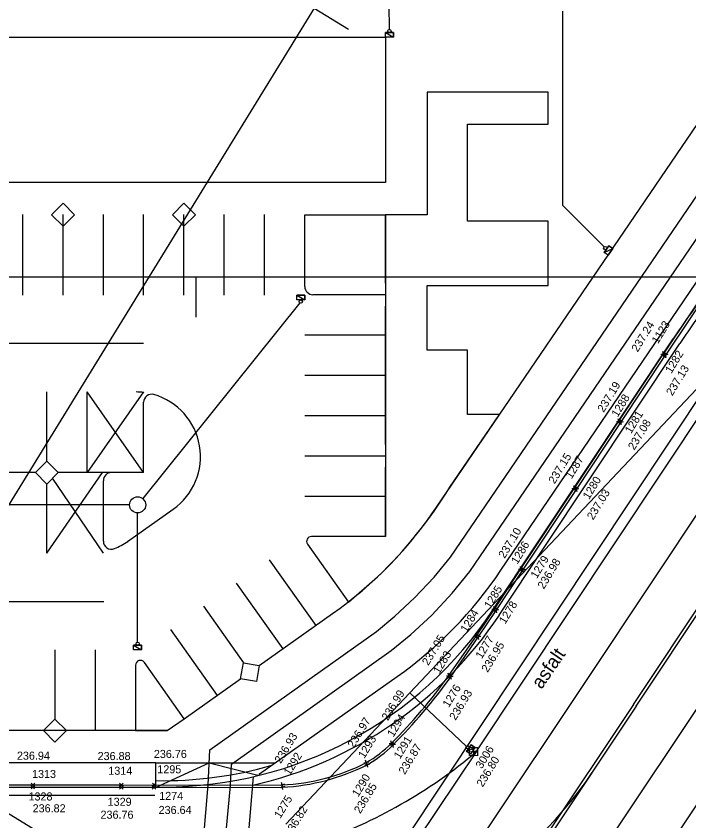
# Model space of a CAD drawing. Extents: x -264205 to -263615, y -1242401 to -1242031.
# Drawn here: x -263824.98 to -263783.24, y -1242303.58 to -1242253.67 of the extents above; entities that cross this region are included whole.
import ezdxf

# ---------------------------------------------------------------- set-up
doc = ezdxf.new("R2010")
doc.units = 0
for name, color, linetype in [('BODY_SYMBOL A CISLO_2-1', 7, 'Continuous'), ('BODY_SYMBOL A CISLO_2-2', 7, 'Continuous'), ('BODY_VYSKA_2-1', 7, 'Continuous'), ('BODY_VYSKA_2-2', 7, 'Continuous'), ('KOORDINACNA_SITUACIA_DSP', 7, 'Continuous'), ('POPIS', 7, 'Continuous'), ('PROJEKT_DRS_TDZ_VODOROVNE', 7, 'Continuous'), ('RAM_NA_TLAC_1-250_SITUACIA_2-1', 7, 'Continuous'), ('RAM_NA_TLAC_1-250_SITUACIA_2-2', 7, 'Continuous'), ('SO_20-1_OBRUBNIKY_DOLNA_HRANA', 7, 'Continuous'), ('SO_20-1_OBRUBNIKY_HORNA_HRANA', 7, 'Continuous'), ('SO_20-1_UV', 7, 'Continuous')]:
    doc.layers.add(name, color=color, linetype=linetype)

msp = doc.modelspace()

# ---------------------------------------------------------------- linework, layer by layer
at = {"layer": 'BODY_SYMBOL A CISLO_2-1'}
for p, q in [((-263824.056, -1242301.597), (-263823.834, -1242301.377)), ((-263823.834, -1242301.597), (-263824.056, -1242301.377)), ((-263824.051, -1242301.454), (-263823.829, -1242301.232)), ((-263823.829, -1242301.454), (-263824.051, -1242301.232)), ((-263818.567, -1242301.463), (-263818.345, -1242301.242)), ((-263818.345, -1242301.463), (-263818.567, -1242301.242)), ((-263818.562, -1242301.606), (-263818.341, -1242301.384)), ((-263818.341, -1242301.606), (-263818.562, -1242301.384)), ((-263816.53, -1242301.615), (-263816.309, -1242301.394)), ((-263816.309, -1242301.615), (-263816.53, -1242301.394)), ((-263816.524, -1242301.468), (-263816.302, -1242301.248)), ((-263816.302, -1242301.468), (-263816.524, -1242301.248))]:
    msp.add_line(p, q, dxfattribs=at)
at = {"layer": 'BODY_SYMBOL A CISLO_2-2'}
for p, q in [((-263784.785, -1242274.779), (-263784.859, -1242274.475)), ((-263784.783, -1242274.775), (-263784.857, -1242274.471)), ((-263784.67, -1242274.59), (-263784.974, -1242274.664)), ((-263784.668, -1242274.586), (-263784.972, -1242274.66)), ((-263784.548, -1242274.667), (-263784.852, -1242274.741)), ((-263784.543, -1242274.66), (-263784.847, -1242274.734)), ((-263784.663, -1242274.856), (-263784.737, -1242274.552)), ((-263784.658, -1242274.849), (-263784.732, -1242274.545)), ((-263787.432, -1242278.753), (-263787.736, -1242278.827)), ((-263787.547, -1242278.942), (-263787.621, -1242278.638)), ((-263787.31, -1242278.835), (-263787.614, -1242278.909)), ((-263787.425, -1242279.024), (-263787.499, -1242278.72)), ((-263790.188, -1242282.911), (-263790.492, -1242282.985)), ((-263790.303, -1242283.1), (-263790.377, -1242282.796)), ((-263790.064, -1242282.985), (-263790.368, -1242283.059)), ((-263790.179, -1242283.174), (-263790.253, -1242282.87)), ((-263793.507, -1242287.918), (-263793.811, -1242287.992)), ((-263793.622, -1242288.107), (-263793.696, -1242287.803)), ((-263793.501, -1242288.186), (-263793.575, -1242287.882)), ((-263793.386, -1242287.997), (-263793.69, -1242288.071)), ((-263795.158, -1242290.407), (-263795.462, -1242290.481)), ((-263795.273, -1242290.596), (-263795.347, -1242290.292)), ((-263795.037, -1242290.487), (-263795.341, -1242290.561)), ((-263795.152, -1242290.676), (-263795.226, -1242290.372)), ((-263796.386, -1242292.251), (-263796.46, -1242291.947)), ((-263796.271, -1242292.062), (-263796.575, -1242292.136)), ((-263796.151, -1242292.143), (-263796.455, -1242292.217)), ((-263796.266, -1242292.332), (-263796.34, -1242292.028)), ((-263798.095, -1242294.725), (-263798.169, -1242294.421)), ((-263797.98, -1242294.536), (-263798.284, -1242294.61)), ((-263797.861, -1242294.617), (-263798.165, -1242294.691)), ((-263797.976, -1242294.806), (-263798.05, -1242294.502)), ((-263801.54, -1242298.73), (-263801.844, -1242298.804)), ((-263801.441, -1242298.833), (-263801.745, -1242298.907)), ((-263801.655, -1242298.919), (-263801.729, -1242298.615)), ((-263801.556, -1242299.022), (-263801.63, -1242298.718)), ((-263796.449, -1242299.249), (-263796.753, -1242299.323)), ((-263796.564, -1242299.438), (-263796.638, -1242299.134)), ((-263803.105, -1242299.929), (-263803.409, -1242300.003)), ((-263803.22, -1242300.118), (-263803.294, -1242299.814)), ((-263803.152, -1242300.246), (-263803.226, -1242299.942)), ((-263803.037, -1242300.057), (-263803.341, -1242300.131)), ((-263808.324, -1242301.307), (-263808.628, -1242301.381)), ((-263808.313, -1242301.451), (-263808.617, -1242301.525)), ((-263808.439, -1242301.496), (-263808.513, -1242301.192)), ((-263808.428, -1242301.64), (-263808.502, -1242301.336))]:
    msp.add_line(p, q, dxfattribs=at)
at = {"layer": 'KOORDINACNA_SITUACIA_DSP'}
for p, q in [((-263822.88, -1242337.914), (-263734.49, -1242204.937)), ((-263794.898, -1242288.032), (-263742.736, -1242211.145)), ((-263798.899, -1242284.125), (-263751.864, -1242215.081)), ((-263801.822, -1242254.497), (-263801.837, -1242252.972)), ((-263791.063, -1242265.427), (-263791.063, -1242253.362)), ((-263802.071, -1242254.697), (-263801.571, -1242254.697)), ((-263802.071, -1242254.987), (-263802.071, -1242254.697)), ((-263802.071, -1242254.697), (-263801.571, -1242254.987)), ((-263802.071, -1242254.697), (-263801.571, -1242254.987)), ((-263801.571, -1242254.697), (-263802.071, -1242254.697)), ((-263801.571, -1242254.987), (-263802.071, -1242254.987)), ((-263801.571, -1242254.697), (-263801.571, -1242254.987)), ((-263801.571, -1242254.987), (-263801.571, -1242254.697)), ((-263788.502, -1242267.989), (-263791.063, -1242265.427)), ((-263807.068, -1242270.447), (-263807.068, -1242265.987)), ((-263807.068, -1242265.987), (-263802.068, -1242265.987)), ((-263802.068, -1242270.24), (-263802.068, -1242265.987)), ((-263788.491, -1242268.322), (-263788.207, -1242267.91)), ((-263788.207, -1242267.91), (-263788.491, -1242268.322)), ((-263788.207, -1242267.91), (-263787.968, -1242268.075)), ((-263787.968, -1242268.075), (-263788.207, -1242267.91)), ((-263788.491, -1242268.322), (-263787.968, -1242268.075)), ((-263788.491, -1242268.322), (-263787.968, -1242268.075)), ((-263788.252, -1242268.487), (-263788.491, -1242268.322)), ((-263787.968, -1242268.075), (-263788.252, -1242268.487)), ((-263807.568, -1242270.982), (-263807.068, -1242270.982)), ((-263807.568, -1242271.272), (-263807.568, -1242270.982)), ((-263807.568, -1242270.982), (-263807.068, -1242271.272)), ((-263807.568, -1242270.982), (-263807.068, -1242271.272)), ((-263807.068, -1242270.982), (-263807.568, -1242270.982)), ((-263807.068, -1242270.982), (-263807.068, -1242271.272)), ((-263807.068, -1242271.272), (-263807.068, -1242270.982)), ((-263802.068, -1242270.947), (-263806.568, -1242270.947)), ((-263807.38, -1242271.45), (-263817.128, -1242283.593)), ((-263807.068, -1242271.272), (-263807.568, -1242271.272)), ((-263802.068, -1242280.24), (-263802.068, -1242271.654)), ((-263795.416, -1242290.541), (-263784.214, -1242273.68)), ((-263780.353, -1242274.236), (-263808.248, -1242303.783)), ((-263817.068, -1242281.982), (-263817.068, -1242277.62)), ((-263817.068, -1242281.982), (-263819.068, -1242281.982)), ((-263802.068, -1242285.947), (-263802.068, -1242281.654)), ((-263819.568, -1242286.231), (-263819.568, -1242282.482)), ((-263817.941, -1242283.982), (-263870.324, -1242283.982)), ((-263817.941, -1242283.982), (-263870.324, -1242283.982)), ((-263818.06, -1242286.248), (-263815.232, -1242284.248)), ((-263817.441, -1242292.492), (-263817.441, -1242284.482)), ((-263809.895, -1242293.947), (-263805.344, -1242290.728)), ((-263817.691, -1242292.692), (-263817.191, -1242292.692)), ((-263817.691, -1242292.982), (-263817.691, -1242292.692)), ((-263817.691, -1242292.692), (-263817.191, -1242292.982)), ((-263817.691, -1242292.692), (-263817.191, -1242292.982)), ((-263817.191, -1242292.692), (-263817.691, -1242292.692)), ((-263817.191, -1242292.982), (-263817.691, -1242292.982)), ((-263817.191, -1242292.692), (-263817.191, -1242292.982)), ((-263817.191, -1242292.982), (-263817.191, -1242292.692)), ((-263814.555, -1242297.242), (-263811.05, -1242294.763)), ((-263809.875, -1242300.669), (-263801.342, -1242294.634)), ((-263797.048, -1242298.952), (-263800.558, -1242295.638)), ((-263815.601, -1242297.982), (-263917.08, -1242297.982)), ((-263797.029, -1242299.286), (-263796.75, -1242298.871)), ((-263796.75, -1242298.871), (-263797.029, -1242299.286)), ((-263796.75, -1242298.871), (-263796.51, -1242299.032)), ((-263796.51, -1242299.032), (-263796.75, -1242298.871)), ((-263797.029, -1242299.286), (-263796.51, -1242299.032)), ((-263797.029, -1242299.286), (-263796.51, -1242299.032)), ((-263796.788, -1242299.448), (-263797.029, -1242299.286)), ((-263796.51, -1242299.032), (-263796.788, -1242299.448)), ((-263816.308, -1242299.982), (-263918.049, -1242299.982)), ((-263816.308, -1242301.482), (-263816.308, -1242299.982)), ((-263816.308, -1242299.982), (-263808.904, -1242299.982)), ((-263809.906, -1242300.757), (-263809.875, -1242300.669)), ((-263914.08, -1242301.482), (-263815.822, -1242301.482))]:
    msp.add_line(p, q, dxfattribs=at)
for points in [[(-263802.068, -1242263.988), (-263834.256, -1242263.984), (-263849.468, -1242254.985), (-263802.068, -1242254.987)], [(-263822.068, -1242265.279), (-263821.361, -1242265.986), (-263822.068, -1242266.694), (-263822.775, -1242265.986)], [(-263814.568, -1242265.279), (-263813.861, -1242265.986), (-263814.568, -1242266.693), (-263815.275, -1242265.986)], [(-263823.068, -1242281.275), (-263822.361, -1242281.982), (-263823.068, -1242282.689), (-263823.775, -1242281.982)], [(-263810.881, -1242293.778), (-263809.895, -1242293.947), (-263810.064, -1242294.932), (-263811.05, -1242294.763)], [(-263822.568, -1242297.275), (-263821.861, -1242297.982), (-263822.568, -1242298.689), (-263823.275, -1242297.982)]]:
    msp.add_lwpolyline(points, close=True, dxfattribs=at)
for points in [[(-263798.064, -1242282.882), (-263794.987, -1242278.383), (-263796.968, -1242278.382), (-263796.968, -1242274.382), (-263799.468, -1242274.382), (-263799.468, -1242270.382), (-263791.968, -1242270.382), (-263791.968, -1242266.382), (-263796.968, -1242266.382), (-263796.968, -1242260.382), (-263791.968, -1242260.382), (-263791.968, -1242258.382), (-263799.468, -1242258.382), (-263799.468, -1242265.987), (-263802.068, -1242265.987)], [(-263802.068, -1242265.987), (-263802.068, -1242270.24), (-263802.068, -1242270.947), (-263802.068, -1242271.654), (-263802.068, -1242273.447), (-263802.068, -1242275.947), (-263802.068, -1242278.447), (-263802.068, -1242280.24), (-263802.068, -1242280.24), (-263802.068, -1242281.654), (-263802.068, -1242283.447), (-263802.068, -1242285.947), (-263806.656, -1242285.943)], [(-263806.901, -1242286.416), (-263804.349, -1242290.024), (-263802.552, -1242288.44)], [(-263817.568, -1242293.926), (-263817.568, -1242297.982), (-263815.601, -1242297.982), (-263814.555, -1242297.242), (-263817.023, -1242293.753)], [(-263816.327, -1242301.51), (-263813.002, -1242299.982), (-263809.906, -1242300.757)]]:
    msp.add_lwpolyline(points, dxfattribs=at)
for centre, radius in [((-263801.821, -1242254.597), 0.1), ((-263788.431, -1242268.059), 0.1), ((-263807.318, -1242271.372), 0.1), ((-263817.441, -1242283.982), 0.5), ((-263817.441, -1242292.592), 0.1), ((-263796.975, -1242299.02), 0.1)]:
    msp.add_circle(centre, radius, dxfattribs=at)
for centre, radius, start, end in [((-263806.568, -1242270.447), 0.5, 180, 270), ((-263742.568, -1242301.35), 50, 142.3688, 146.3992), ((-263816.568, -1242277.62), 0.5, 73.8446, 180), ((-263817.542, -1242280.982), 4, 305.2702, 73.8446), ((-263819.068, -1242282.482), 0.5, 90, 180), ((-263821.806, -1242268.304), 27.86, 313.7192, 328.4502), ((-263820.069, -1242269.909), 25.5, 305.2702, 326.1165), ((-263806.656, -1242286.243), 0.3, 89.9436, 215.2702), ((-263819.068, -1242286.231), 0.5, 180, 291.8332), ((-263820.369, -1242282.982), 4, 291.8332, 305.2702), ((-263816.067, -1242273.815), 25.5, 305.2702, 326.1165), ((-263815.822, -1242276.982), 24.5, 270, 326.3992), ((-263817.268, -1242293.926), 0.3, 35.2702, 180), ((-263815.836, -1242276.967), 24.119, 268.8787, 286.1798)]:
    msp.add_arc(centre, radius, start, end, dxfattribs=at)
at = {"layer": 'PROJEKT_DRS_TDZ_VODOROVNE'}
for p, q in [((-263824.568, -1242270.982), (-263824.568, -1242265.982)), ((-263822.068, -1242270.982), (-263822.068, -1242265.982)), ((-263819.568, -1242270.982), (-263819.568, -1242265.982)), ((-263817.068, -1242270.982), (-263817.068, -1242265.982)), ((-263814.568, -1242270.982), (-263814.568, -1242265.982)), ((-263812.068, -1242270.982), (-263812.068, -1242265.982)), ((-263809.568, -1242270.982), (-263809.568, -1242265.982)), ((-263807.068, -1242273.447), (-263802.068, -1242273.447)), ((-263796.435, -1242299.302), (-263779.243, -1242273.429)), ((-263817.068, -1242273.982), (-263917.477, -1242273.982)), ((-263795, -1242290.817), (-263783.807, -1242273.971)), ((-263789.385, -1242294.564), (-263776.537, -1242275.228)), ((-263807.068, -1242275.947), (-263802.068, -1242275.947)), ((-263823.068, -1242281.275), (-263823.068, -1242276.982)), ((-263820.568, -1242281.982), (-263820.568, -1242276.982)), ((-263817.068, -1242276.982), (-263820.568, -1242281.982)), ((-263817.068, -1242281.982), (-263820.568, -1242276.982)), ((-263786.678, -1242296.363), (-263773.83, -1242277.027)), ((-263786.512, -1242296.474), (-263773.663, -1242277.138)), ((-263807.068, -1242278.447), (-263802.068, -1242278.447)), ((-263818.504, -1242350.278), (-263771.023, -1242279.037)), ((-263807.068, -1242280.947), (-263802.068, -1242280.947)), ((-263823.775, -1242281.982), (-263829.861, -1242281.982)), ((-263823.068, -1242286.982), (-263819.614, -1242281.982)), ((-263818.068, -1242281.982), (-263822.361, -1242281.982)), ((-263819.568, -1242286.982), (-263822.714, -1242282.336)), ((-263823.068, -1242286.982), (-263823.068, -1242282.689)), ((-263807.068, -1242283.447), (-263802.068, -1242283.447)), ((-263809.278, -1242287.386), (-263806.39, -1242291.468)), ((-263811.319, -1242288.829), (-263808.432, -1242292.912)), ((-263819.531, -1242289.994), (-263917.477, -1242289.994)), ((-263813.36, -1242290.273), (-263810.881, -1242293.778)), ((-263813.36, -1242290.273), (-263810.881, -1242293.778)), ((-263815.401, -1242291.717), (-263812.514, -1242295.799)), ((-263822.568, -1242292.982), (-263822.568, -1242297.275)), ((-263820.068, -1242292.982), (-263820.068, -1242297.982)), ((-263824.083, -1242346.553), (-263789.385, -1242294.564)), ((-263786.678, -1242296.363), (-263806.091, -1242325.442)), ((-263786.512, -1242296.474), (-263805.925, -1242325.553)), ((-263796.435, -1242299.302), (-263802.558, -1242308.383)), ((-263781.086, -1242300.054), (-263792.626, -1242317.328)), ((-263810.915, -1242308.545), (-263810.255, -1242300.841)), ((-263913.857, -1242301.982), (-263816.374, -1242301.982))]:
    msp.add_line(p, q, dxfattribs=at)
for points in [[(-263831.211, -1242326.873), (-263816.19, -1242319.41), (-263814.291, -1242315.804), (-263813.06, -1242301.353), (-263812.968, -1242299.181), (-263802.618, -1242291.831), (-263801.478, -1242290.893), (-263800.257, -1242289.755), (-263799.049, -1242288.464), (-263798.027, -1242287.218), (-263749.798, -1242216.488), (-263742.736, -1242211.145)], [(-263830.6, -1242328.105), (-263815.26, -1242320.378), (-263813.062, -1242316.188), (-263811.682, -1242301.389), (-263811.608, -1242300.055), (-263801.705, -1242293.023), (-263800.489, -1242292.021), (-263799.197, -1242290.817), (-263797.92, -1242289.454), (-263796.825, -1242288.118), (-263748.697, -1242217.536), (-263741.831, -1242212.341)]]:
    msp.add_lwpolyline(points, dxfattribs=at)
for centre, radius, start, end in [((-263742.161, -1242301.641), 50, 142.3688, 146.3992), ((-263817.542, -1242280.982), 4, 83.1966, 90), ((-263815.822, -1242276.982), 25, 282.7622, 326.3992), ((-263816.477, -1242275.476), 31.135, 289.1139, 310.0684), ((-263809.228, -1242287.295), 24, 270.4085, 326.3969)]:
    msp.add_arc(centre, radius, start, end, dxfattribs=at)
at = {"layer": 'RAM_NA_TLAC_1-250_SITUACIA_2-1'}
msp.add_line((-263813.833, -1242269.835), (-263813.833, -1242272.335), dxfattribs=at)
msp.add_lwpolyline([(-264151.333, -1242269.835), (-263718.833, -1242269.835), (-263718.833, -1242344.085), (-264151.333, -1242344.085)], close=True, dxfattribs=at)
at = {"layer": 'RAM_NA_TLAC_1-250_SITUACIA_2-2'}
msp.add_line((-263806.493, -1242253.175), (-263804.363, -1242254.485), dxfattribs=at)
msp.add_lwpolyline([(-263834.004, -1242297.889), (-263756.71, -1242172.264), (-263693.471, -1242211.173), (-263770.766, -1242336.799)], close=True, dxfattribs=at)
at = {"layer": 'SO_20-1_OBRUBNIKY_DOLNA_HRANA'}
for points in [[(-263753.129, -1242233.288), (-263758.555, -1242239.941), (-263762.992, -1242245.362), (-263766.809, -1242249.987), (-263769.992, -1242253.855), (-263773.801, -1242258.482), (-263776.883, -1242263.085), (-263780.236, -1242268.055), (-263784.695, -1242274.697)], [(-263798.013, -1242294.654), (-263796.303, -1242292.18), (-263795.189, -1242290.524), (-263793.538, -1242288.034), (-263790.216, -1242283.022), (-263787.462, -1242278.872), (-263784.7, -1242274.704)], [(-263913.884, -1242301.489), (-263907.893, -1242301.489), (-263900.89, -1242301.488), (-263893.898, -1242301.483), (-263886.917, -1242301.473), (-263879.922, -1242301.465), (-263872.91, -1242301.469), (-263865.929, -1242301.465), (-263859.932, -1242301.473), (-263850.941, -1242301.471), (-263843.947, -1242301.471), (-263836.942, -1242301.481), (-263829.943, -1242301.484), (-263823.945, -1242301.487), (-263818.452, -1242301.495), (-263816.42, -1242301.504)], [(-263816.42, -1242301.504), (-263808.465, -1242301.488)]]:
    msp.add_lwpolyline(points, dxfattribs=at)
for centre, major_axis, ratio, start_param, end_param in [((-263825.45, -1242274.928), (18.854, 28.266), 0.994545, 4.514508, 4.677485), ((-263807.174, -1242293.246), (7.914, -0.383), 0.999893, 5.287754, 5.542292), ((-263809.043, -1242288.645), (12.659, 2.536), 0.995625, 4.560279, 4.986171)]:
    msp.add_ellipse(centre, major_axis=major_axis, ratio=ratio, start_param=start_param, end_param=end_param, dxfattribs=at)
at = {"layer": 'SO_20-1_OBRUBNIKY_HORNA_HRANA'}
for points in [[(-263784.822, -1242274.627), (-263781.463, -1242269.63), (-263778.122, -1242264.669), (-263773.885, -1242258.373), (-263770.104, -1242253.768), (-263766.29, -1242249.13), (-263762.466, -1242244.514), (-263758.662, -1242239.844), (-263753.256, -1242233.184)], [(-263798.132, -1242294.573), (-263796.423, -1242292.099), (-263795.31, -1242290.444), (-263793.659, -1242287.955), (-263790.34, -1242282.948), (-263787.584, -1242278.79), (-263784.82, -1242274.623)], [(-263913.884, -1242301.344), (-263907.893, -1242301.343), (-263900.896, -1242301.344), (-263893.895, -1242301.338), (-263886.916, -1242301.328), (-263879.921, -1242301.324), (-263872.911, -1242301.324), (-263865.928, -1242301.325), (-263859.931, -1242301.327), (-263850.935, -1242301.324), (-263843.941, -1242301.331), (-263836.939, -1242301.332), (-263829.941, -1242301.342), (-263823.94, -1242301.343), (-263818.456, -1242301.352), (-263816.413, -1242301.358)], [(-263816.413, -1242301.358), (-263808.476, -1242301.344)]]:
    msp.add_lwpolyline(points, dxfattribs=at)
for centre, major_axis, ratio, start_param, end_param in [((-263824.958, -1242275.34), (19.218, 27.206), 0.990974, 4.5401, 4.705457), ((-263807.23, -1242293.156), (3.846, 6.885), 0.999705, 4.179295, 4.429956), ((-263809.03, -1242288.701), (12.476, 2.408), 0.995918, 4.56612, 4.994215)]:
    msp.add_ellipse(centre, major_axis=major_axis, ratio=ratio, start_param=start_param, end_param=end_param, dxfattribs=at)
at = {"layer": 'SO_20-1_UV'}
msp.add_line((-263796.601, -1242299.286), (-263796.601, -1242299.286), dxfattribs=at)
msp.add_lwpolyline([(-263796.851, -1242299.284), (-263796.849, -1242299.034), (-263796.349, -1242299.038), (-263796.353, -1242299.538), (-263796.853, -1242299.534), (-263796.851, -1242299.284), (-263796.351, -1242299.288)], dxfattribs=at)

# ---------------------------------------------------------------- texts
at = {"layer": 'BODY_SYMBOL A CISLO_2-1'}
for s, p in [('1313', (-263823.992, -1242300.921)), ('1314', (-263819.26, -1242300.719)), ('1295', (-263816.219, -1242300.63)), ('1328', (-263824.211, -1242302.315)), ('1274', (-263816.102, -1242302.281)), ('1329', (-263819.301, -1242302.644))]:
    msp.add_text(s, height=0.5, dxfattribs=at).set_placement(p)
at = {"layer": 'BODY_SYMBOL A CISLO_2-2'}
for s, p in [('1123', (-263785.163, -1242274.036)), ('1282', (-263784.327, -1242275.869)), ('1288', (-263787.658, -1242278.584)), ('1281', (-263786.825, -1242279.605)), ('1287', (-263790.518, -1242282.412)), ('1280', (-263789.436, -1242283.684)), ('1286', (-263793.883, -1242287.702)), ('1279', (-263792.675, -1242288.594)), ('1285', (-263795.563, -1242290.455)), ('1278', (-263794.635, -1242291.412)), ('1284', (-263797.024, -1242291.934)), ('1277', (-263796.092, -1242293.572)), ('1283', (-263798.725, -1242294.504)), ('1276', (-263798.134, -1242296.588)), ('1294', (-263801.574, -1242298.421)), ('1293', (-263803.377, -1242299.747)), ('1291', (-263801.167, -1242299.786)), ('3006', (-263796.087, -1242300.385)), ('1292', (-263807.995, -1242300.804)), ('1290', (-263803.756, -1242302.134)), ('1275', (-263808.588, -1242303.466))]:
    msp.add_text(s, height=0.5, rotation=58.5501, dxfattribs=at).set_placement(p)
at = {"layer": 'BODY_VYSKA_2-1'}
for s, p in [('236.94', (-263824.93, -1242299.787)), ('236.88', (-263819.925, -1242299.809)), ('236.76', (-263816.434, -1242299.679)), ('236.82', (-263823.956, -1242303.049)), ('236.76', (-263819.743, -1242303.446)), ('236.64', (-263816.14, -1242303.151))]:
    msp.add_text(s, height=0.5, dxfattribs=at).set_placement(p)
at = {"layer": 'BODY_VYSKA_2-2'}
for s, p in [('237.24', (-263786.417, -1242274.541)), ('237.13', (-263784.267, -1242277.254)), ('237.19', (-263788.524, -1242278.283)), ('237.08', (-263786.629, -1242280.621)), ('237.15', (-263791.568, -1242282.72)), ('237.03', (-263789.178, -1242284.953)), ('237.10', (-263794.67, -1242287.34)), ('236.98', (-263792.239, -1242289.244)), ('237.05', (-263799.409, -1242293.982)), ('236.95', (-263795.723, -1242294.408)), ('236.93', (-263797.715, -1242297.378)), ('236.99', (-263801.915, -1242297.404)), ('236.97', (-263804.031, -1242299.103)), ('236.93', (-263808.562, -1242300.061)), ('236.87', (-263800.864, -1242300.742)), ('236.80', (-263796.03, -1242301.52)), ('236.85', (-263803.63, -1242303.169)), ('236.82', (-263807.942, -1242304.593))]:
    msp.add_text(s, height=0.5, rotation=58.5501, dxfattribs=at).set_placement(p)
at = {"layer": 'POPIS'}
msp.add_text('asfalt', height=0.8438, rotation=55.5208, dxfattribs=at).set_placement((-263792.384, -1242295.46))

doc.saveas('drawing.dxf')
